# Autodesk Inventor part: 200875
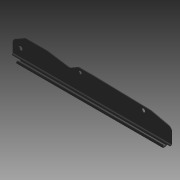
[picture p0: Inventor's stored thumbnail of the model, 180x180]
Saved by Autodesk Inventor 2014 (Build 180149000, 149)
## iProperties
Created: 2007-10
Part Number: 200875
Document SubType Name: Modeling
Designer: TH
Density: 7.85 g/cm^3
Mass: 510.334 g
Surface Area: 671.811 cm^2
Volume: 65.0106 cm^3
Material: Steel
Description: RAIL SIDE - RIGHT INNER
Appearance: Dark Gray
Component Category: Lower Component
Author: TH
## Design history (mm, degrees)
node "200468" dims "d1" = 10
body "Solid1"
tag "TaggingFeature3"
feature "DerivedBody::D-200468" dims "d1" = 10
